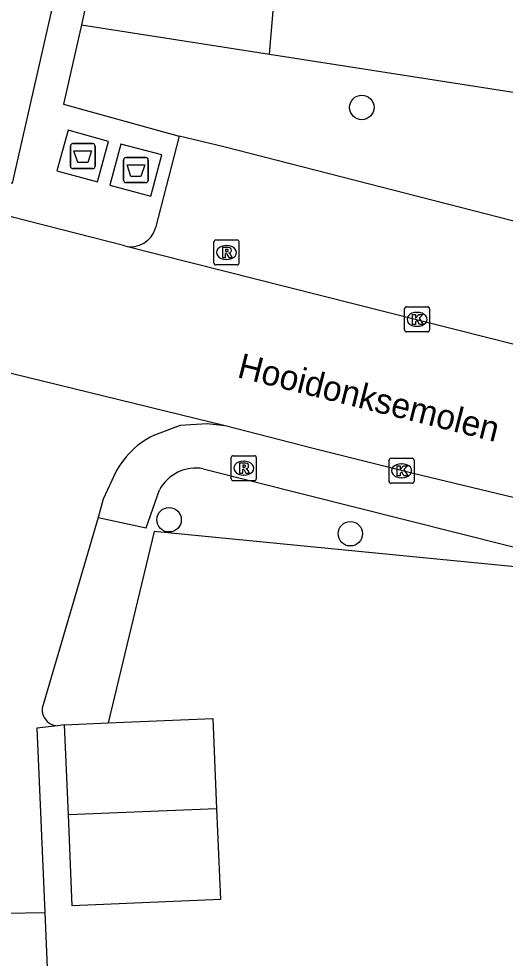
# Model space of a CAD drawing. Extents: x 161243 to 161752, y 384138 to 384885.
# Drawn here: x 161335.77 to 161355.25, y 384281.86 to 384319.46 of the extents above; entities that cross this region are included whole.
import ezdxf

# ---------------------------------------------------------------- set-up
doc = ezdxf.new("R2010")
doc.units = 0
for name, color, linetype in [('IMGEO_Afval_apart_plaats', 7, 'Continuous'), ('IMGEO_Boom', 7, 'Continuous'), ('IMGEO_Groenvoorziening', 7, 'Continuous'), ('IMGEO_Kolk', 7, 'Continuous'), ('IMGEO_Openbare_ruimte_label', 7, 'Continuous'), ('IMGEO_Pand', 7, 'Continuous'), ('IMGEO_Parkeervlak_open', 7, 'Continuous'), ('IMGEO_Rijbaan_lokaal_open', 7, 'Continuous'), ('IMGEO_Rioolput', 7, 'Continuous'), ('IMGEO_Voetpad_gesloten', 7, 'Continuous'), ('IMGEO_Voetpad_open', 7, 'Continuous')]:
    doc.layers.add(name, color=color, linetype=linetype)

msp = doc.modelspace()

# ---------------------------------------------------------------- linework, layer by layer
at = {"layer": 'IMGEO_Afval_apart_plaats'}
for p, q in [((161337.939, 384314.467), (161338.729, 384314.467)), ((161338.729, 384314.467), (161337.939, 384314.467)), ((161337.839, 384313.567), (161337.839, 384314.367)), ((161337.839, 384314.367), (161337.839, 384313.567)), ((161338.829, 384314.367), (161338.829, 384313.567)), ((161338.829, 384313.567), (161338.829, 384314.367)), ((161339.968, 384313.008), (161339.968, 384313.808)), ((161339.968, 384313.808), (161339.968, 384313.008)), ((161340.068, 384313.908), (161340.858, 384313.908)), ((161340.858, 384313.908), (161340.068, 384313.908)), ((161340.958, 384313.808), (161340.958, 384313.008)), ((161340.958, 384313.008), (161340.958, 384313.808)), ((161338.729, 384313.467), (161337.939, 384313.467)), ((161337.939, 384313.467), (161338.729, 384313.467)), ((161340.858, 384312.908), (161340.068, 384312.908)), ((161340.068, 384312.908), (161340.858, 384312.908))]:
    msp.add_line(p, q, dxfattribs=at)
for points in [[(161337.982, 384314.181), (161338.686, 384314.181), (161338.537, 384313.711), (161338.131, 384313.711), (161337.982, 384314.181)], [(161340.111, 384313.622), (161340.815, 384313.622), (161340.666, 384313.152), (161340.26, 384313.152), (161340.111, 384313.622)]]:
    msp.add_lwpolyline(points, dxfattribs=at)
for centre, start, end in [((161337.939, 384314.367), 90, 180), ((161337.939, 384314.367), 90, 180), ((161338.729, 384314.367), 0, 90), ((161338.729, 384314.367), 360, 90), ((161340.068, 384313.808), 90, 180), ((161340.068, 384313.808), 90, 180), ((161340.858, 384313.808), 0, 90), ((161340.858, 384313.808), 360, 90), ((161337.939, 384313.567), 180, 270), ((161337.939, 384313.567), 180, 270), ((161338.729, 384313.567), 270, 0), ((161338.729, 384313.567), 270, 0), ((161340.068, 384313.008), 180, 270), ((161340.068, 384313.008), 180, 270), ((161340.858, 384313.008), 270, 0), ((161340.858, 384313.008), 270, 0)]:
    msp.add_arc(centre, 0.1, start, end, dxfattribs=at)
at = {"layer": 'IMGEO_Boom'}
for centre in [(161349.508, 384315.915), (161341.792, 384299.412), (161349.048, 384298.852)]:
    msp.add_circle(centre, 0.489, dxfattribs=at)
at = {"layer": 'IMGEO_Groenvoorziening'}
for points in [[(161345.806, 384318.051), (161348.839, 384353.935)], [(161338.281, 384319.226), (161345.806, 384318.051)], [(161345.806, 384318.051), (161360.974, 384315.683), (161359.706, 384310.307)], [(161364.129, 384294.223), (161355.716, 384295.962), (161355.65, 384297.533), (161341.191, 384298.94), (161339.356, 384291.278)], [(161337.608, 384291.205), (161337.32, 384291.17)]]:
    msp.add_lwpolyline(points, dxfattribs=at)
at = {"layer": 'IMGEO_Kolk'}
for p, q in [((161351.219, 384307.008), (161351.219, 384307.86)), ((161351.294, 384307.934), (161352.146, 384307.934)), ((161351.707, 384307.714), (161351.732, 384307.714)), ((161352.22, 384307.86), (161352.22, 384307.008)), ((161352.146, 384306.934), (161351.294, 384306.934)), ((161351.73, 384307.154), (161351.705, 384307.154)), ((161350.602, 384300.947), (161350.602, 384301.799)), ((161350.677, 384301.873), (161351.529, 384301.873)), ((161351.09, 384301.653), (161351.115, 384301.653)), ((161351.603, 384301.799), (161351.603, 384300.947)), ((161351.113, 384301.093), (161351.088, 384301.093)), ((161351.529, 384300.873), (161350.677, 384300.873))]:
    msp.add_line(p, q, dxfattribs=at)
for points in [[(161351.219, 384307.008), (161351.219, 384307.86)], [(161351.294, 384307.934), (161352.146, 384307.934)], [(161352.22, 384307.86), (161352.22, 384307.008)], [(161351.54, 384307.634), (161351.663, 384307.634), (161351.663, 384307.483), (161351.793, 384307.634), (161351.957, 384307.634), (161351.811, 384307.483), (161351.964, 384307.234), (161351.812, 384307.234), (161351.727, 384307.398), (161351.663, 384307.331), (161351.663, 384307.234), (161351.54, 384307.234), (161351.54, 384307.634)], [(161352.146, 384306.934), (161351.294, 384306.934)], [(161350.602, 384300.947), (161350.602, 384301.799)], [(161350.677, 384301.873), (161351.529, 384301.873)], [(161351.603, 384301.799), (161351.603, 384300.947)], [(161350.923, 384301.573), (161351.046, 384301.573), (161351.046, 384301.422), (161351.176, 384301.573), (161351.34, 384301.573), (161351.194, 384301.422), (161351.347, 384301.173), (161351.195, 384301.173), (161351.11, 384301.337), (161351.046, 384301.27), (161351.046, 384301.173), (161350.923, 384301.173), (161350.923, 384301.573)], [(161351.529, 384300.873), (161350.677, 384300.873)]]:
    msp.add_lwpolyline(points, dxfattribs=at)
for centre, start, end in [((161351.296, 384307.858), 91.552, 178.448), ((161351.296, 384307.858), 91.552, 178.448), ((161352.144, 384307.858), 1.552, 88.448), ((161352.144, 384307.858), 1.552, 88.448), ((161351.296, 384307.01), 181.552, 268.448), ((161351.296, 384307.01), 181.552, 268.448), ((161352.144, 384307.01), 271.552, 358.448), ((161352.144, 384307.01), 271.552, 358.448), ((161350.679, 384301.797), 91.552, 178.448), ((161350.679, 384301.797), 91.552, 178.448), ((161351.527, 384301.797), 1.552, 88.448), ((161351.527, 384301.797), 1.552, 88.448), ((161350.679, 384300.949), 181.552, 268.448), ((161350.679, 384300.949), 181.552, 268.448), ((161351.527, 384300.949), 271.552, 358.448), ((161351.527, 384300.949), 271.552, 358.448)]:
    msp.add_arc(centre, 0.0765, start, end, dxfattribs=at)
for centre, major_axis, ratio, start_param, end_param in [((161351.706, 384307.434), (-0.387, 0.002), 0.722429, 4.712389, 7.853982), ((161351.731, 384307.434), (-0.39, 0.002), 0.717154, 1.570796, 4.712389), ((161351.089, 384301.373), (-0.387, 0.002), 0.722429, 4.712389, 7.853982), ((161351.114, 384301.373), (-0.39, 0.002), 0.717154, 1.570796, 4.712389)]:
    msp.add_ellipse(centre, major_axis=major_axis, ratio=ratio, start_param=start_param, end_param=end_param, dxfattribs=at)
at = {"layer": 'IMGEO_Pand'}
for points in [[(161337.608, 384291.205), (161339.356, 384291.278)], [(161337.758, 384287.607), (161337.608, 384291.205)], [(161339.356, 384291.278), (161343.541, 384291.452), (161343.692, 384287.843)], [(161343.692, 384287.843), (161343.843, 384284.212), (161337.91, 384283.965), (161337.758, 384287.607)], [(161343.692, 384287.843), (161337.758, 384287.607)]]:
    msp.add_lwpolyline(points, dxfattribs=at)
at = {"layer": 'IMGEO_Parkeervlak_open'}
msp.add_lwpolyline([(161359.706, 384310.307), (161343.987, 384314.34), (161342.197, 384314.772)], dxfattribs=at)
at = {"layer": 'IMGEO_Rijbaan_lokaal_open'}
for points in [[(161340.013, 384310.37), (161334.145, 384311.868), (161312.768, 384317.162), (161299.409, 384320.514), (161296.499, 384321.254)], [(161340.013, 384310.37), (161359.736, 384305.395)], [(161344.034, 384303.169), (161332.498, 384305.981)], [(161344.034, 384303.169), (161343.315, 384303.25), (161342.239, 384303.19), (161341.207, 384302.802)], [(161366.059, 384297.781), (161355.95, 384300.205), (161351.506, 384301.273), (161347.56, 384302.264), (161344.034, 384303.169)], [(161339.5, 384300.988), (161339.149, 384300.233), (161338.948, 384299.496)], [(161338.948, 384299.496), (161336.713, 384291.871)], [(161331.745, 384292.799), (161333.39, 384292.341), (161333.505, 384290.009), (161333.601, 384287.108), (161333.712, 384285.206), (161333.749, 384283.665), (161335.259, 384283.661), (161336.819, 384283.698)], [(161337.32, 384291.17), (161336.501, 384291.074), (161336.819, 384283.698)]]:
    msp.add_lwpolyline(points, dxfattribs=at)
for centre, radius, start, end in [((161342.692, 384299.695), 3.444, 115.5396, 157.9416), ((161337.341, 384291.801), 0.631, 173.6444, 268.1346)]:
    msp.add_arc(centre, radius, start, end, dxfattribs=at)
at = {"layer": 'IMGEO_Rioolput'}
for p, q in [((161343.589, 384309.684), (161343.589, 384310.536)), ((161343.664, 384310.61), (161344.516, 384310.61)), ((161344.077, 384310.39), (161344.102, 384310.39)), ((161344.59, 384310.536), (161344.59, 384309.684)), ((161344.516, 384309.61), (161343.664, 384309.61)), ((161344.1, 384309.83), (161344.075, 384309.83)), ((161344.28, 384301.05), (161344.28, 384301.902)), ((161344.355, 384301.976), (161345.207, 384301.976)), ((161344.768, 384301.756), (161344.793, 384301.756)), ((161345.281, 384301.902), (161345.281, 384301.05)), ((161345.207, 384300.976), (161344.355, 384300.976)), ((161344.791, 384301.196), (161344.766, 384301.196))]:
    msp.add_line(p, q, dxfattribs=at)
for points in [[(161343.589, 384309.684), (161343.589, 384310.536)], [(161343.664, 384310.61), (161344.516, 384310.61)], [(161344.178, 384310.308), (161343.926, 384310.31), (161343.926, 384309.91)], [(161344.59, 384310.536), (161344.59, 384309.684)], [(161343.926, 384309.91), (161344.05, 384309.91), (161344.05, 384310.072), (161344.061, 384310.072)], [(161344.104, 384310.229), (161344.05, 384310.229), (161344.05, 384310.148)], [(161344.05, 384310.148), (161344.102, 384310.148)], [(161344.108, 384310.043), (161344.179, 384309.91), (161344.319, 384309.91), (161344.254, 384310.036)], [(161344.516, 384309.61), (161343.664, 384309.61)], [(161344.28, 384301.05), (161344.28, 384301.902)], [(161344.355, 384301.976), (161345.207, 384301.976)], [(161344.869, 384301.674), (161344.617, 384301.676), (161344.617, 384301.276)], [(161345.281, 384301.902), (161345.281, 384301.05)], [(161344.617, 384301.276), (161344.741, 384301.276), (161344.741, 384301.438), (161344.752, 384301.438)], [(161344.795, 384301.595), (161344.741, 384301.595), (161344.741, 384301.514)], [(161344.741, 384301.514), (161344.793, 384301.514)], [(161344.799, 384301.409), (161344.87, 384301.276), (161345.01, 384301.276), (161344.945, 384301.402)], [(161345.207, 384300.976), (161344.355, 384300.976)]]:
    msp.add_lwpolyline(points, dxfattribs=at)
for centre, radius, start, end in [((161343.666, 384310.534), 0.0765, 91.552, 178.448), ((161343.666, 384310.534), 0.0765, 91.552, 178.448), ((161344.177, 384310.198), 0.109, 350.3612, 89.416), ((161344.514, 384310.534), 0.0765, 1.552, 88.448), ((161344.514, 384310.534), 0.0765, 1.552, 88.448), ((161344.06, 384310.019), 0.0533, 26.0293, 88.6989), ((161344.086, 384310.337), 0.19, 274.7715, 282.9687), ((161344.11, 384310.133), 0.0964, 77.0061, 93.1865), ((161344.124, 384310.19), 0.0378, 276.6634, 79.6772), ((161344.175, 384310.198), 0.112, 277.5842, 350.9817), ((161344.159, 384309.983), 0.108, 29.5134, 73.7905), ((161343.666, 384309.686), 0.0765, 181.552, 268.448), ((161343.666, 384309.686), 0.0765, 181.552, 268.448), ((161344.514, 384309.686), 0.0765, 271.552, 358.448), ((161344.514, 384309.686), 0.0765, 271.552, 358.448), ((161344.357, 384301.9), 0.0765, 91.552, 178.448), ((161344.357, 384301.9), 0.0765, 91.552, 178.448), ((161344.868, 384301.564), 0.109, 350.3612, 89.416), ((161345.205, 384301.9), 0.0765, 1.552, 88.448), ((161345.205, 384301.9), 0.0765, 1.552, 88.448), ((161344.751, 384301.385), 0.0533, 26.0293, 88.6989), ((161344.777, 384301.703), 0.19, 274.7715, 282.9687), ((161344.801, 384301.499), 0.0964, 77.0061, 93.1865), ((161344.815, 384301.556), 0.0378, 276.6634, 79.6772), ((161344.866, 384301.564), 0.112, 277.5842, 350.9817), ((161344.85, 384301.349), 0.108, 29.5134, 73.7905), ((161344.357, 384301.052), 0.0765, 181.552, 268.448), ((161344.357, 384301.052), 0.0765, 181.552, 268.448), ((161345.205, 384301.052), 0.0765, 271.552, 358.448), ((161345.205, 384301.052), 0.0765, 271.552, 358.448)]:
    msp.add_arc(centre, radius, start, end, dxfattribs=at)
for centre, major_axis, ratio, start_param, end_param in [((161344.076, 384310.11), (-0.387, 0.002), 0.722429, 4.712389, 7.853982), ((161344.101, 384310.11), (-0.39, 0.002), 0.717154, 1.570796, 4.712389), ((161344.767, 384301.476), (-0.387, 0.002), 0.722429, 4.712389, 7.853982), ((161344.792, 384301.476), (-0.39, 0.002), 0.717154, 1.570796, 4.712389)]:
    msp.add_ellipse(centre, major_axis=major_axis, ratio=ratio, start_param=start_param, end_param=end_param, dxfattribs=at)
at = {"layer": 'IMGEO_Voetpad_gesloten'}
for points in [[(161339.366, 384314.556), (161337.747, 384315.001), (161337.302, 384313.383), (161338.921, 384312.938), (161339.366, 384314.556)], [(161341.5, 384314.016), (161339.863, 384314.452), (161339.423, 384312.8), (161341.06, 384312.364), (161341.5, 384314.016)]]:
    msp.add_lwpolyline(points, dxfattribs=at)
at = {"layer": 'IMGEO_Voetpad_open'}
for points in [[(161295.885, 384325.211), (161295.467, 384325.102), (161295.374, 384323.02), (161335.524, 384312.89), (161338.358, 384325.391)], [(161339.428, 384325.279), (161339.593, 384325.267), (161338.281, 384319.226)], [(161338.281, 384319.226), (161337.862, 384317.338), (161337.568, 384316.046), (161342.197, 384314.772)], [(161342.197, 384314.772), (161341.253, 384311.101)], [(161343.158, 384301.452), (161365.595, 384295.806)], [(161338.948, 384299.496), (161340.871, 384299.087), (161341.404, 384300.609)], [(161336.819, 384283.698), (161338.239, 384250), (161340.006, 384208.085), (161341.148, 384208.134)]]:
    msp.add_lwpolyline(points, dxfattribs=at)
for centre, radius, start, end in [((161340.26, 384311.368), 1.028, 256.0742, 344.9659), ((161342.862, 384299.822), 1.657, 79.7112, 151.6282)]:
    msp.add_arc(centre, radius, start, end, dxfattribs=at)

# ---------------------------------------------------------------- texts
at = {"layer": 'IMGEO_Openbare_ruimte_label'}
msp.add_text('Hooidonksemolen', height=1, rotation=345.936, dxfattribs=at).set_placement((161344.479, 384305.124))

doc.saveas('drawing.dxf')
